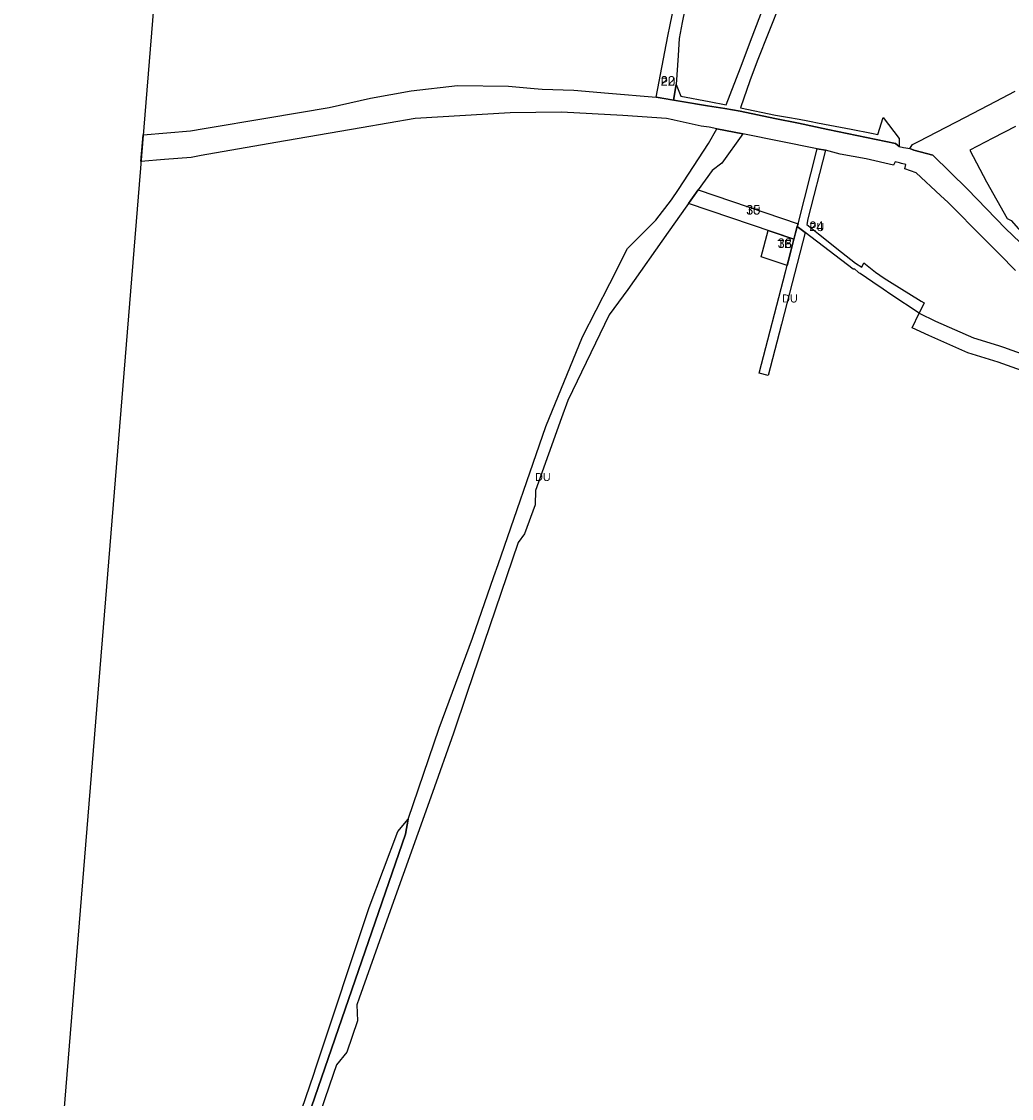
# Model space of a CAD drawing. Extents: x -545758 to -541641, y -1153152 to -1149975.
# Drawn here: x -544753 to -544135, y -1152056 to -1151383 of the extents above; entities that cross this region are included whole.
import ezdxf

# ---------------------------------------------------------------- set-up
doc = ezdxf.new("R2010")
doc.units = 0
for name, color, linetype in [('90310013', 7, 'Continuous'), ('90320013', 7, 'Continuous'), ('90380013', 7, 'Continuous'), ('90380023', 7, 'Continuous'), ('90400023', 7, 'Continuous'), ('90450013', 7, 'Continuous'), ('90450023', 7, 'Continuous'), ('ID_navrh', 7, 'Continuous')]:
    doc.layers.add(name, color=color, linetype=linetype)

msp = doc.modelspace()

# ---------------------------------------------------------------- linework, layer by layer
at = {"layer": '90310013'}
msp.add_lwpolyline([(-544571.74, -1152060.98), (-544513.04, -1151890.62), (-544511.33, -1151881.16), (-544492.05, -1151824.34), (-544471.2, -1151768.07), (-544457.88, -1151729.54), (-544455.29, -1151722.05), (-544425.47, -1151635.75), (-544402.51, -1151579.84), (-544385.47, -1151546.37), (-544374.44, -1151524.6), (-544356.79, -1151506.85), (-544346.93, -1151494.3), (-544346.911, -1151494.272), (-544342.67, -1151487.777), (-544323.939, -1151459.097), (-544323.85, -1151458.96), (-544318.6, -1151449.9), (-544302.52, -1151452.98), (-544315.45, -1151471.39), (-544321.64, -1151475.91), (-544330.23, -1151488.03), (-544348.98, -1151514.49), (-544374.27, -1151550.18), (-544385.88, -1151566.12), (-544411.63, -1151619.63), (-544415.57, -1151630.49), (-544431.97, -1151675.83), (-544432.02, -1151684.69), (-544438.68, -1151702.96), (-544442.81, -1151708.38), (-544474.71, -1151802.71), (-544483.08, -1151827.46), (-544496.26, -1151864.52), (-544523.61, -1151941.41), (-544525.9, -1151947.83), (-544541.95, -1151992.96), (-544543.4, -1151997.05), (-544543.02, -1152007.12), (-544549.76, -1152026.71), (-544556.17, -1152034.56), (-544560.42, -1152047.27), (-544590.33, -1152134.84)], dxfattribs=at)
msp.add_lwpolyline([(-544275.88, -1151539.22), (-544268.404, -1151510.817), (-544263.51, -1151514.56), (-544278.36, -1151571.97), (-544285.39, -1151599.09), (-544286.65, -1151603.93), (-544292.132, -1151602.506)], close=True, dxfattribs=at)
at = {"layer": '90320013'}
msp.add_lwpolyline([(-544132.12, -1151538.41), (-544142.25, -1151528.08), (-544150.65, -1151519.52), (-544158.78, -1151511.45), (-544167.46, -1151502.76), (-544174.15, -1151495.92), (-544179.11, -1151491.44), (-544194.22, -1151477.43), (-544201.35, -1151474.81), (-544200.59, -1151472.14), (-544203.29, -1151471.45), (-544204.65, -1151471.1), (-544207.36, -1151470.4), (-544208.32, -1151472.48), (-544225.45, -1151468.6), (-544241.72, -1151465.67), (-544250.9, -1151463.17), (-544255.94, -1151462.38), (-544302.52, -1151452.98), (-544318.6, -1151449.9), (-544323.36, -1151448.87), (-544328.51, -1151448.1), (-544345.38, -1151444.48), (-544346.19, -1151444.28), (-544350.17, -1151443.45), (-544377.46, -1151441.48), (-544415.66, -1151439.36), (-544447.61, -1151439.82), (-544506.92, -1151443.28), (-544540.71, -1151449.17), (-544593.95, -1151458.46), (-544640.54, -1151466.58), (-544646.97, -1151467.7), (-544663.43, -1151469.03), (-544678.286, -1151470.229), (-544676.935, -1151453.593), (-544647.37, -1151451.12), (-544638.67, -1151449.66), (-544598.93, -1151442.97), (-544560.82, -1151436.56), (-544534.87, -1151430.66), (-544509.45, -1151426.08), (-544480.64, -1151422.82), (-544448.69, -1151423.1), (-544432.64, -1151424.59), (-544427.72, -1151425.05), (-544407.86, -1151425.74), (-544386.22, -1151427.51), (-544356.61, -1151430.05), (-544324.56, -1151435.4), (-544313.64, -1151437.21), (-544304.11, -1151438.8), (-544282.51, -1151443.31), (-544267.69, -1151446.4), (-544249.31, -1151450.22), (-544207.08, -1151458.91), (-544204.74, -1151460.96), (-544202.02, -1151461.44), (-544200.63, -1151461.69), (-544198.11, -1151462.14), (-544195.57, -1151463.08), (-544183.82, -1151466.2), (-544162.07, -1151487.63), (-544138.44, -1151512.18), (-544129.2, -1151520.88)], dxfattribs=at)
at = {"layer": '90380013'}
msp.add_lwpolyline([(-544569.04, -1152036.59), (-544535.68, -1151936.25), (-544517.9, -1151888.93), (-544511.33, -1151881.16), (-544513.04, -1151890.62), (-544571.74, -1152060.98), (-544630.44, -1152231.35), (-544697.22, -1152411.89), (-544699.22, -1152404.28), (-544651.83, -1152276.93), (-544609.92, -1152155.93), (-544599.8, -1152126.71), (-544570.31, -1152040.39)], close=True, dxfattribs=at)
at = {"layer": '90380023'}
msp.add_lwpolyline([(-544270.501, -1151518.784), (-544336.264, -1151496.546), (-544330.23, -1151488.03), (-544267.95, -1151509.09), (-544268.404, -1151510.817)], close=True, dxfattribs=at)
msp.add_lwpolyline([(-544122.596, -1151602.964), (-544142.902, -1151595.719), (-544145.696, -1151594.853), (-544161.996, -1151589.82), (-544186.221, -1151579.065), (-544196.616, -1151574.109), (-544192.36, -1151565.06), (-544182.04, -1151569.98), (-544158.48, -1151580.44), (-544142.74, -1151585.3), (-544139.74, -1151586.23), (-544118.3, -1151593.88)], dxfattribs=at)
at = {"layer": '90400023'}
msp.add_lwpolyline([(-544841.973, -1152250.685), (-544744.745, -1151053.026), (-544738.859, -1151050.292), (-544703.7, -1151033.96), (-544687.067, -1151029.768), (-544678.11, -1151027.51), (-544642.403, -1151028.226), (-544742.287, -1152258.607)], dxfattribs=at)
msp.add_lwpolyline([(-544274.838, -1151535.263), (-544290.981, -1151529.804), (-544286.643, -1151513.325), (-544270.501, -1151518.784)], close=True, dxfattribs=at)
at = {"layer": '90450013'}
for points in [[(-544279.01, -1151370.9), (-544293.39, -1151407.59), (-544298.08, -1151419.85), (-544303.98, -1151436.74), (-544282.08, -1151441.25), (-544274.55, -1151442.49), (-544267.18, -1151443.7), (-544261.88, -1151444.9), (-544259.72, -1151445.33), (-544255.75, -1151446.11), (-544248.07, -1151447.62), (-544234.82, -1151450.04), (-544222.02, -1151452.57), (-544218.14, -1151453.31), (-544214.78, -1151442.66), (-544204.92, -1151455.91), (-544204.74, -1151460.96), (-544207.08, -1151458.91), (-544249.31, -1151450.22), (-544267.69, -1151446.4), (-544282.51, -1151443.31), (-544304.11, -1151438.8), (-544313.64, -1151437.21), (-544324.56, -1151435.4), (-544345.636, -1151431.882), (-544344.02, -1151422.2), (-544341.1, -1151429.5), (-544323.5, -1151432.72), (-544312.77, -1151434.93), (-544303.94, -1151411.78), (-544296.52, -1151392.31), (-544289.48, -1151373.85)], [(-544129.2, -1151520.88), (-544138.44, -1151512.18), (-544162.07, -1151487.63), (-544183.82, -1151466.2), (-544195.57, -1151463.08), (-544198.11, -1151462.14), (-544196.56, -1151459.57), (-544192.77, -1151457.73), (-544175.55, -1151448.78), (-544163.41, -1151442.49), (-544144.7, -1151432.67), (-544132.32, -1151426.21)], [(-544132.09, -1151448.33), (-544146.42, -1151455.75), (-544160.63, -1151463.23), (-544150.25, -1151482.96), (-544137.37, -1151505.81), (-544134.86, -1151507.04), (-544125.68, -1151517.57)]]:
    msp.add_lwpolyline(points, dxfattribs=at)
at = {"layer": '90450023'}
msp.add_lwpolyline([(-544329.9, -1151332.33), (-544340.23, -1151383.48), (-544342.25, -1151393.49), (-544342.89, -1151403.92), (-544344.02, -1151422.2), (-544345.636, -1151431.882), (-544356.61, -1151430.05), (-544349.21, -1151391.85), (-544347.81, -1151384.94), (-544342.65, -1151359.51)], dxfattribs=at)
msp.add_lwpolyline([(-544210, -1151553.26), (-544214.8, -1151550.04), (-544221.23, -1151545.74), (-544229.19, -1151540.31), (-544230.06, -1151539.72), (-544230.64, -1151539.08), (-544232.47, -1151537.6), (-544233.62, -1151537.42), (-544263.51, -1151514.56), (-544268.404, -1151510.817), (-544267.95, -1151509.09), (-544255.94, -1151462.38), (-544250.9, -1151463.17), (-544261.82, -1151506.13), (-544262.51, -1151509.53), (-544255.11, -1151515.44), (-544240.84, -1151526.96), (-544232.03, -1151533.8), (-544228.04, -1151536.23), (-544226.79, -1151533.59), (-544219.64, -1151539.31), (-544214.27, -1151543.1), (-544210.79, -1151545.24), (-544191.1, -1151557.51), (-544189.294, -1151558.541), (-544192.36, -1151565.06)], close=True, dxfattribs=at)

# ---------------------------------------------------------------- texts
at = {"layer": '90310013'}
msp.add_text('DU', height=5, dxfattribs=at).set_placement((-544277.821, -1151558.332))
msp.add_text('DU', height=5, rotation=0, dxfattribs=at).set_placement((-544432.081, -1151669.868))
at = {"layer": '90380023'}
msp.add_text('TU', height=5, rotation=0, dxfattribs=at).set_placement((-544300.365, -1151503.407))
at = {"layer": '90400023'}
msp.add_text('TE', height=5, rotation=0, dxfattribs=at).set_placement((-544280.741, -1151524.294))
at = {"layer": '90450023'}
for rotation, p in [(360, (-544353.74, -1151422.882)), (0, (-544260.936, -1151513.72))]:
    msp.add_text('PU', height=5, rotation=rotation, dxfattribs=at).set_placement(p)
at = {"layer": 'ID_navrh'}
for s, rotation, p in [('22', 360, (-544353.74, -1151422.882)), ('35', 0, (-544300.365, -1151503.407)), ('24', 0, (-544260.936, -1151513.72)), ('38', 0, (-544280.741, -1151524.294))]:
    msp.add_text(s, height=6, rotation=rotation, dxfattribs=at).set_placement(p)

doc.saveas('drawing.dxf')
